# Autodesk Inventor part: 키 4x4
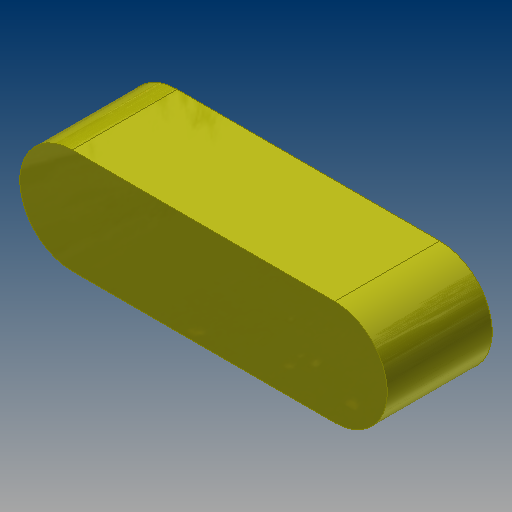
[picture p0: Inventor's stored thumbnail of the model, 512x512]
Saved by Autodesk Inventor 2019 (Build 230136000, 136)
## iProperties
Created: 2014-10
Part Number: 키 4x4
Document SubType Name: Modeling
Designer: KYOUNG IL JANG
Density: 7.86 g/cm^3
Mass: 1.65269 g
Surface Area: 2.35398 cm^2
Volume: 0.210265 cm^3
Material: 강철, 연강
Appearance: 노란색
Author: SeoGD™ [www.esajin.kr]
Revision Number: 1
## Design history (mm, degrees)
sketch "스케치1"
  geometry: L1 (-5, -2)-(5, -2); L2 (5, 2)-(-5, 2); A1 r 2 centre (5, 0) between (5, -2) and (5, 2); A2 r 2 centre (-5, 0) between (-5, 2) and (-5, -2); 2 further points
  constraints: 4 end point, 4 point on circle, 4 tangent, 2 centre point, 1 horizontal, 1 horizontal alignment, 1 midpoint, 1 parallel, 1 vertical alignment
  dimensions: "d0" = 4 distance between parallel lines of L1 L2; "d1" = 14 dimension on A1 A2
extrude "돌출1" new body sketch "스케치1" stored distance "d2" = 4; taper "d3" = 0 deg
node "솔리드1"
